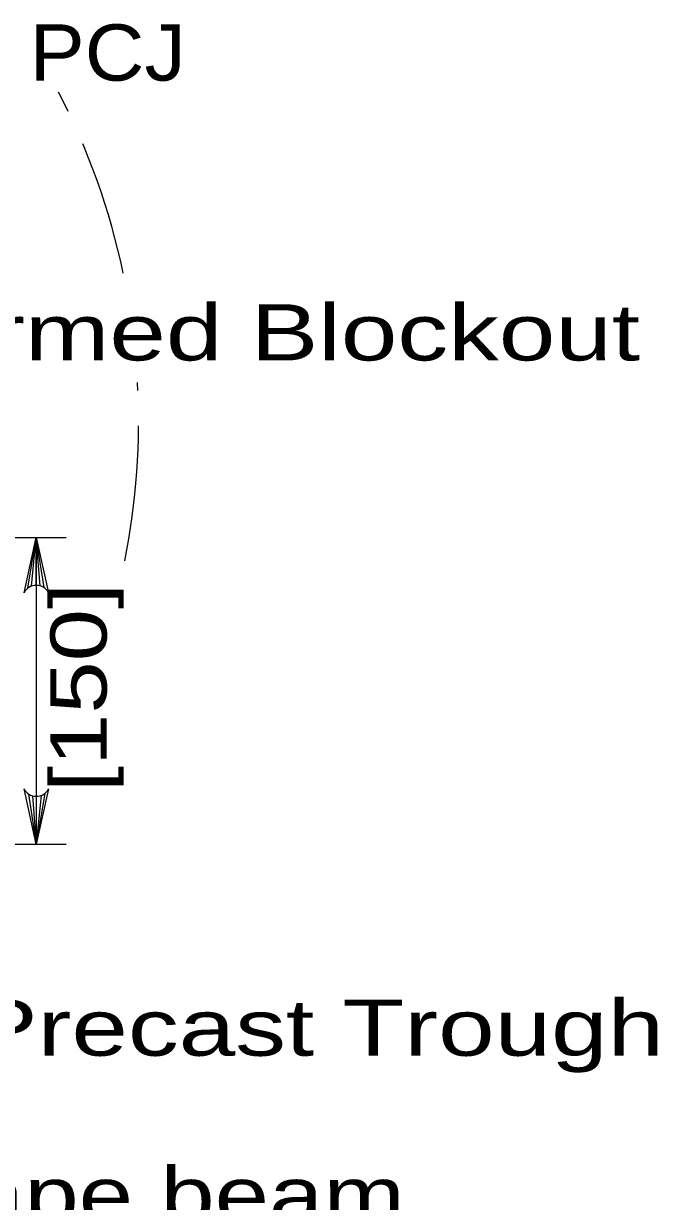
# Model space of a CAD drawing. Extents: x -1431.2 to -1397.2, y -1045.1 to -1001.1.
# Drawn here: x -1412.824 to -1411.034, y -1035.128 to -1031.802 of the extents above; entities that cross this region are included whole.
import ezdxf
from ezdxf.enums import TextEntityAlignment as Align

# ---------------------------------------------------------------- set-up
doc = ezdxf.new("R2010")
doc.units = 0
doc.header["$LTSCALE"] = 0.064
doc.linetypes.add('LONG_DASHED', pattern=[7.5, 6, -1.5])
doc.layers.add('1', color=7, linetype='Continuous', lineweight=13)

msp = doc.modelspace()

# ---------------------------------------------------------------- linework, layer by layer
at = {"layer": '1'}
for p, q in [((-1414.21442, -1033.2535), (-1412.70433, -1033.2535)), ((-1412.8125, -1033.39642), (-1412.78825, -1033.2535)), ((-1412.80233, -1033.391), (-1412.78825, -1033.2535)), ((-1412.78825, -1033.2535), (-1412.78825, -1034.119)), ((-1412.78825, -1033.3885), (-1412.78825, -1033.2535)), ((-1412.77717, -1033.38992), (-1412.78825, -1033.2535)), ((-1412.76625, -1033.39475), (-1412.78825, -1033.2535)), ((-1412.81017, -1033.97783), (-1412.78825, -1034.119)), ((-1412.764, -1033.97617), (-1412.78825, -1034.119)), ((-1412.79933, -1033.98258), (-1412.78825, -1034.119)), ((-1412.77417, -1033.98158), (-1412.78825, -1034.119)), ((-1412.78825, -1033.98408), (-1412.78825, -1034.119)), ((-1414.20317, -1034.119), (-1412.70433, -1034.119))]:
    msp.add_line(p, q, dxfattribs=at)
for points in [[(-1412.82292, -1033.4095), (-1412.78825, -1033.2535), (-1412.75358, -1033.4095)], [(-1412.75358, -1033.96308), (-1412.78825, -1034.119), (-1412.82292, -1033.96308)]]:
    msp.add_lwpolyline(points, dxfattribs=at)
at = {"layer": '1', "linetype": 'LONG_DASHED'}
for start, end in [(11.90444, 27.39489), (348.64848, 3.06023)]:
    msp.add_arc((-1414.51372, -1032.92267), 2.01436, start, end, dxfattribs=at)
at = {"layer": '1'}
for centre, major_axis in [((-1412.7882, -1033.42209), (0.03741, 0)), ((-1412.78827, -1033.95045), (-0.03741, 0))]:
    msp.add_ellipse(centre, major_axis=major_axis, ratio=0.9, start_param=0.3855052, end_param=2.7561184, dxfattribs=at)

# ---------------------------------------------------------------- texts
at = {"layer": '1', "width": 1.1}
msp.add_text('PCJ', height=0.1588, dxfattribs=at).set_placement((-1412.58683, -1031.963), align=Align.CENTER)
at = {"layer": '1'}
for s, width, p in [('Formed Blockout', 1.35, (-1413.25058, -1032.75325)), ('Precast Trough', 1.35, (-1412.97567, -1034.71683)), ('S shape beam', 1.3, (-1413.52792, -1035.18958))]:
    msp.add_text(s, height=0.1588, dxfattribs=dict(at, width=width)).set_placement(p)
at = {"layer": '1', "width": 1.25}
msp.add_text('[150]', height=0.1588, rotation=90, dxfattribs=at).set_placement((-1412.58975, -1033.67683), align=Align.CENTER)

doc.saveas('drawing.dxf')
